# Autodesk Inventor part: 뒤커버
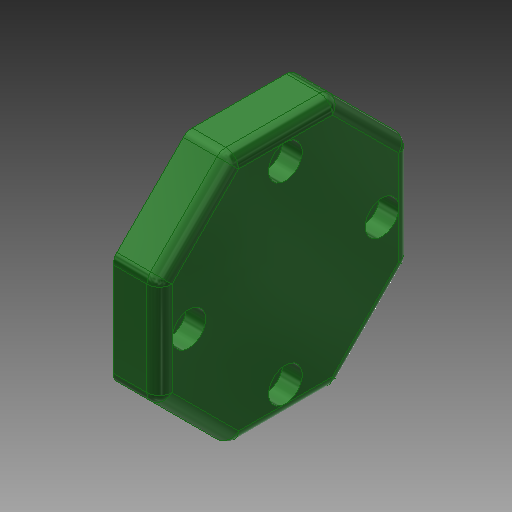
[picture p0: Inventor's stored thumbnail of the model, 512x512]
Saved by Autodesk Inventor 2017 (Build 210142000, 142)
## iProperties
Created: 2015-11
Part Number: 뒤커버
Material: 알루미늄 6061
Document SubType Name: Modeling
Designer: mduedu
Density: 1 g/cm^3
Appearance: 매끄러움 - 짙은 산림 녹색
Author: mduedu
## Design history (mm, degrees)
sketch "스케치5" dims "d66" = 60
  geometry: L1 (12.426, 30)-(30, 12.426); L2 (30, 12.426)-(30, -12.426); L3 (30, -12.426)-(12.426, -30); L4 (12.426, -30)-(-12.426, -30); L5 (-12.426, -30)-(-30, -12.426); L6 (-30, -12.426)-(-30, 12.426); L7 (-30, 12.426)-(-12.426, 30); L8 (-12.426, 30)-(12.426, 30); 4 further points
  constraints: 16 end point, 2 coincident, 2 vertical alignment, 1 midpoint, 19 other
extrude "돌출2" new body sketch "스케치5" distance "d67" = 11; taper "d68" = 0 deg
sketch "스케치6"
  geometry: C1 r 16 at (0, 0); 1 further point
  constraints: 1 centre point, 1 coincident
  dimensions: "d69" = 32 diameter of C1
extrude "돌출3" join sketch "스케치6" distance "d70" = 3; taper "d71" = 0 deg
hole "구멍5" diameter "d74" = 25; stored, may be unused: countersink angle "d78" = 90 deg, drill point angle "d80" = 0 deg; dims "d72" = 10, "d73" = 10, "d75" = 6, "d76" = 4, "d77" = 2, "d79" = 10
fillet "모깎기7" dims "d81" = 3
fillet "모깎기8" dims "d82" = 3
fillet "모깎기9" dims "d83" = 3
fillet "모깎기10" dims "d84" = 0.3
sketch "스케치7" dims "d85" = 46
  geometry: 3 further points
  constraints: 2 vertical alignment, 1 coincident, 2 other
hole "구멍6" sketch "스케치7" at (0, 23) diameter "d86" = 4.5; stored, may be unused: countersink angle "d90" = 90 deg, drill point angle "d92" = 0 deg; dims "d87" = 6, "d88" = 8, "d89" = 4.6, "d91" = 10
node "솔리드2"
pattern_circular "원형 패턴3" dims angle "d94" = 360 deg
